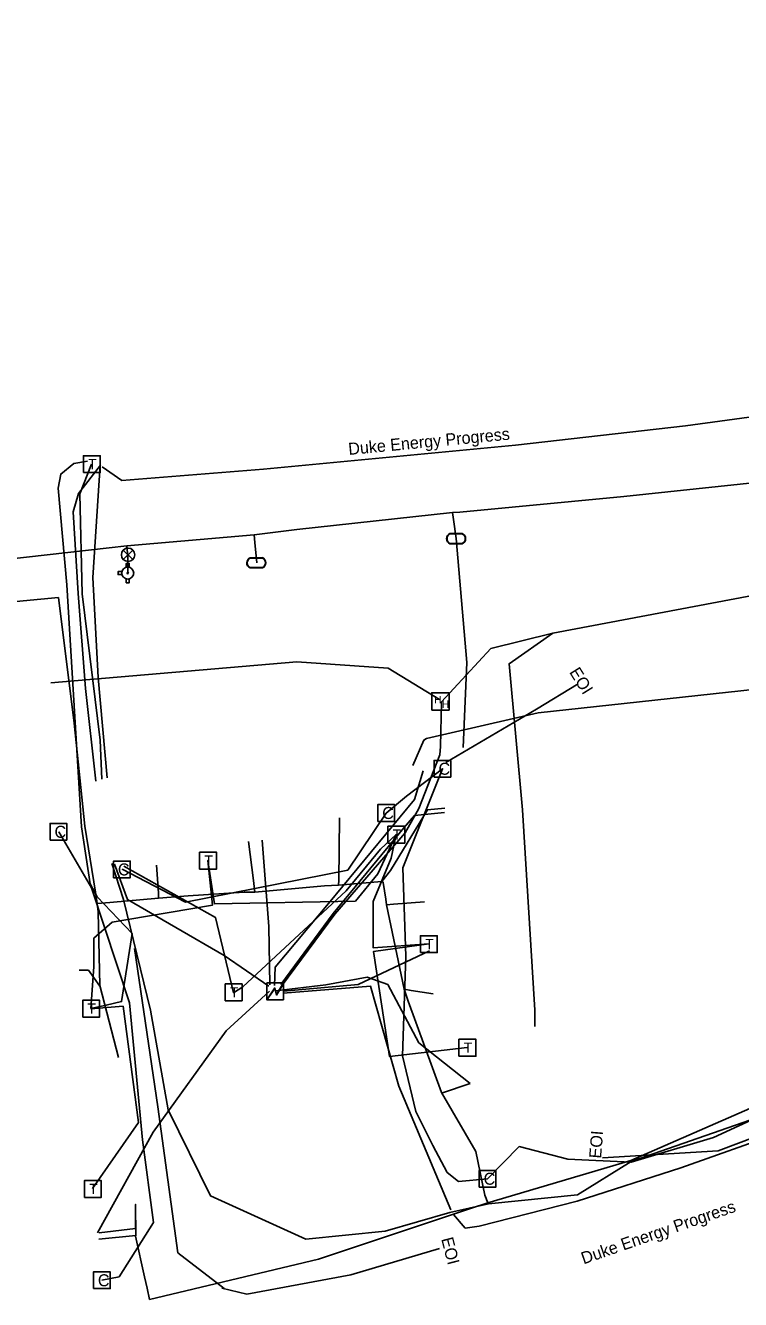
# Model space of a CAD drawing. Extents: x 2070721 to 2083340, y 729290 to 737883.
# Drawn here: x 2079795.9 to 2080033.2, y 734847.8 to 735270.6 of the extents above; entities that cross this region are included whole.
import ezdxf

# ---------------------------------------------------------------- set-up
doc = ezdxf.new("R2010")
doc.units = 0
for name, color, linetype in [('Exist Utilities Gas UG Line SUE LOS B', 7, 'Continuous'), ('Exist Utilities Other Pole Text', 7, 'Continuous'), ('Exist Utilities Other Unknown UG SUE LOS B', 7, 'Continuous'), ('Exist Utilities Power Hand Hole CELL', 7, 'Continuous'), ('Exist Utilities Power Transformer CELL', 7, 'Continuous'), ('Exist Utilities Power UG Cable SUE LOS B', 7, 'Continuous'), ('Exist Utilities Power UG Cable SUE LOS B Text', 7, 'Continuous'), ('Exist Utilities Telephone Pedestal CELL', 7, 'Continuous'), ('Exist Utilities Telephone UG Cable SUE LOS C', 7, 'Continuous'), ('Exist Utilities TV Pedestal CELL', 7, 'Continuous'), ('Exist Utilities TV Pedestal Text', 7, 'Continuous'), ('Exist Utilities TV UG Cable SUE LOS C', 7, 'Continuous'), ('Exist Utilities Water Fire Hydrant CELL', 7, 'Continuous'), ('Exist Utilities Water Meter CELL', 7, 'Continuous'), ('Exist Utilities Water UG Line SUE LOS B', 7, 'Continuous'), ('Exist Utilities Water Valve CELL', 7, 'Continuous')]:
    doc.layers.add(name, color=color, linetype=linetype)

msp = doc.modelspace()

# ---------------------------------------------------------------- linework, layer by layer
at = {"layer": 'Exist Utilities Gas UG Line SUE LOS B'}
for p, q in [((2079820.55, 734952.02), (2079826.75, 734928.16)), ((2079943.49, 734919.53), (2079934, 734916.34))]:
    msp.add_line(p, q, dxfattribs=at)
for points in [[(2079414.85, 735046.76), (2079454.13, 735049.75), (2079543.65, 735057.22), (2079599.14, 735062.31), (2079679.58, 735068.56), (2079761.05, 735076.49), (2079806.84, 735080.78), (2079812.03, 735039.09)], [(2079819.7, 734979.23), (2079819.1, 734983), (2079815.63, 735004.94), (2079812.03, 735039.09)], [(2079914.14, 734986.5), (2079917.04, 734990.19), (2079929.28, 735010.34), (2079935.11, 735010.83)], [(2079899.81, 734985.29), (2079899.84, 734986.97), (2079900.15, 735007.66)], [(2079871.98, 734983.03), (2079871.52, 734986.88), (2079869.95, 734999.87)], [(2079840.03, 734981.01), (2079840.09, 734982.77), (2079839.39, 734992.02)], [(2079899.81, 734985.29), (2079895.09, 734985.08), (2079871.98, 734983.03)], [(2079914.14, 734986.5), (2079899.81, 734985.29)], [(2079915.7, 734978.81), (2079915.49, 734980.72), (2079914.64, 734986.24), (2079914.14, 734986.5)], [(2079840.03, 734981.01), (2079823.9, 734979.6), (2079819.7, 734979.23)], [(2079871.98, 734983.03), (2079868.44, 734983.01), (2079849.88, 734981.79), (2079840.03, 734981.01)], [(2079819.7, 734979.23), (2079819.99, 734976.46), (2079820.55, 734952.02)], [(2079915.7, 734978.81), (2079918.01, 734979), (2079928.3, 734979.85)], [(2079921.53, 734950.78), (2079915.7, 734978.81)], [(2079820.54, 734951.86), (2079816.8, 734957.12), (2079813.68, 734957.12)], [(2079921.53, 734950.78), (2079923.85, 734950.38), (2079931.17, 734949.3)], [(2079949.32, 734879.97), (2079948.37, 734882.46), (2079945.4, 734896.93), (2079933.99, 734916.54), (2079922.96, 734946.84), (2079921.53, 734950.78)], [(2079949.32, 734879.97), (2079996.84, 734894.02), (2080044.13, 734914.6), (2080077.42, 734926.53), (2080123.41, 734941.95), (2080133.94, 734945)], [(2079820.34, 734869.93), (2079832.43, 734871.42), (2079832.43, 734879.38), (2079832.53, 734869.03), (2079820.22, 734867.89)], [(2079837.08, 734847.83), (2079893.1, 734861.27), (2079943.95, 734878.14), (2079949.32, 734879.97)], [(2079832.45, 734868.87), (2079835.42, 734855.37)], [(2079835.42, 734855.37), (2079836.25, 734851.6), (2079837.08, 734847.83)]]:
    msp.add_lwpolyline(points, dxfattribs=at)
at = {"layer": 'Exist Utilities Other Unknown UG SUE LOS B'}
for points in [[(2079964.93, 734938.4), (2079964.93, 734943.9), (2079960.87, 735010.33), (2079956.41, 735058.83), (2079970.93, 735068.94)], [(2079861.84, 734851.44), (2079846.5, 734863.35), (2079839.82, 734911.79), (2079832.04, 734964.37)], [(2079861.04, 734851.58), (2079869.33, 734849.63), (2079903.86, 734856.01), (2079933.32, 734864.79)]]:
    msp.add_lwpolyline(points, dxfattribs=at)
at = {"layer": 'Exist Utilities Power Hand Hole CELL'}
msp.add_line((2079933.68, 735046.14), (2079933.68, 735046.14), dxfattribs=at)
msp.add_lwpolyline([(2079930.73, 735043.41), (2079936.48, 735043.41), (2079936.48, 735049.16), (2079930.73, 735049.16), (2079930.73, 735043.41)], dxfattribs=at)
at = {"layer": 'Exist Utilities Power Transformer CELL'}
msp.add_line((2079878.82, 734950.25), (2079878.82, 734950.25), dxfattribs=at)
msp.add_lwpolyline([(2079875.97, 734952.87), (2079881.52, 734952.87), (2079881.52, 734947.31), (2079875.97, 734947.31)], close=True, dxfattribs=at)
for points in [[(2079875.97, 734947.31), (2079878.61, 734951.26), (2079879.24, 734949.05), (2079881.52, 734952.87)], [(2079876.04, 734947.31), (2079878.61, 734951.05), (2079879.2, 734948.87), (2079881.52, 734952.71)]]:
    msp.add_lwpolyline(points, dxfattribs=at)
at = {"layer": 'Exist Utilities Power UG Cable SUE LOS B'}
for points in [[(2079821.33, 735124.13), (2079827.86, 735119.63), (2079874.94, 735123.38), (2079958.5, 735131.34), (2080015, 735137.74), (2080088.94, 735147.78), (2080173.89, 735156.26), (2080200.11, 735169.56), (2080228.49, 735215.43), (2080246.93, 735270.61)], [(2079820.82, 735124.7), (2079813.52, 735115.34), (2079811.73, 735109.27), (2079813.4, 735082.17), (2079815.83, 735050.61), (2079819.25, 735019.8)], [(2079823, 735021), (2079819.99, 735054.23), (2079818.26, 735087.39), (2079820.67, 735124.76)], [(2079970.93, 735068.94), (2080060.68, 735085.85), (2080105.85, 735089.11), (2080166.83, 735095.38), (2080172.93, 735082.78)], [(2079933.65, 735031.31), (2079934.01, 735046.2), (2079950.34, 735063.83), (2079970.93, 735068.94)], [(2079929, 735034.01), (2079966.1, 735042.55), (2080052.65, 735051.87), (2080116.2, 735063.66), (2080127.54, 735054.13)], [(2079933.36, 735046.91), (2079916.26, 735057.31), (2079885.92, 735059.47), (2079804.25, 735052.53)], [(2079880.87, 734951.79), (2079898.59, 734975.74), (2079921.87, 735002.72), (2079926.41, 735010.81), (2079933.42, 735028.58), (2079933.65, 735031.31)], [(2079929, 735034.01), (2079928.11, 735033.48), (2079924.48, 735025.08)], [(2079927.87, 735023.3), (2079924.98, 735013.79), (2079896.42, 734979.23), (2079878.78, 734958.14), (2079878.49, 734952.06)], [(2079935.01, 735009.41), (2079924.98, 735008.45), (2079921.43, 735004.31), (2079897.96, 734975.94), (2079880.59, 734952.34)], [(2079877.01, 734952.22), (2079876.67, 734971.65), (2079874.43, 735000.27)], [(2079949.54, 734879.56), (2079936.72, 734876.68), (2079915.26, 734870.54), (2079888.89, 734867.91), (2079857.32, 734882.19), (2079843.23, 734910.76), (2079837.34, 734943.81), (2079828.44, 734980.63), (2079824.51, 734992.48)], [(2079825.39, 734992.25), (2079829.74, 734980.55), (2079861.87, 734961.95), (2079876.65, 734951.77)], [(2079881.57, 734950.14), (2079906.31, 734952.42), (2079930.02, 734963.54)], [(2079943.45, 734919.54), (2079926.4, 734933.05), (2079916.15, 734952.37), (2079909.35, 734954.83), (2079895.57, 734952.25), (2079878.82, 734950.25)], [(2079881.41, 734949.51), (2079910.44, 734951.78), (2079919.8, 734918.62), (2079937.05, 734877.55)], [(2079876.86, 734950.12), (2079862.49, 734936.96), (2079838.26, 734903.35), (2079819.82, 734869.91)], [(2079949.54, 734879.56), (2079979.11, 734882.53), (2079996.9, 734893.62), (2080046.16, 734910.81), (2080070.87, 734920.4), (2080091.91, 734922.1), (2080094.14, 734922.76), (2080121.97, 734932.67), (2080134.03, 734940.16), (2080135.53, 734941.3), (2080137.12, 734943.43), (2080137.09, 734946.33)], [(2079987.46, 734894.8), (2080025.82, 734897.12), (2080069.48, 734913.65), (2080069.5, 734913.41), (2080092.72, 734923.35), (2080113.03, 734931.23), (2080133.81, 734940.47), (2080134.5, 734941.28), (2080135.67, 734943.18), (2080136.32, 734946.38)], [(2080070.67, 734913.66), (2080046.49, 734903.28), (2080013.44, 734891.52), (2079979.04, 734880.46), (2079946.47, 734872.13), (2079941.84, 734871.56), (2079937.96, 734876.06)]]:
    msp.add_lwpolyline(points, dxfattribs=at)
at = {"layer": 'Exist Utilities Telephone Pedestal CELL'}
for p, q in [((2079817.84, 735125.07), (2079817.84, 735125.07)), ((2079918.9, 735002.11), (2079918.9, 735002.11)), ((2079856.43, 734993.49), (2079856.43, 734993.49)), ((2079929.7, 734965.76), (2079929.7, 734965.76)), ((2079864.91, 734949.77), (2079864.91, 734949.77)), ((2079817.61, 734944.38), (2079817.61, 734944.38)), ((2079942.5, 734931.41), (2079942.5, 734931.41)), ((2079818.16, 734884.53), (2079818.16, 734884.53))]:
    msp.add_line(p, q, dxfattribs=at)
for points in [[(2079815.11, 735122.24), (2079820.71, 735122.24), (2079820.71, 735127.84), (2079815.11, 735127.84), (2079815.11, 735122.24)], [(2079916.18, 734999.28), (2079921.77, 734999.28), (2079921.77, 735004.88), (2079916.18, 735004.88), (2079916.18, 734999.28)], [(2079853.7, 734990.67), (2079859.3, 734990.67), (2079859.3, 734996.26), (2079853.7, 734996.26), (2079853.7, 734990.67)], [(2079926.98, 734962.94), (2079932.57, 734962.94), (2079932.57, 734968.53), (2079926.98, 734968.53), (2079926.98, 734962.94)], [(2079862.18, 734946.95), (2079867.78, 734946.95), (2079867.78, 734952.54), (2079862.18, 734952.54), (2079862.18, 734946.95)], [(2079814.88, 734941.56), (2079820.48, 734941.56), (2079820.48, 734947.15), (2079814.88, 734947.15), (2079814.88, 734941.56)], [(2079939.78, 734928.58), (2079945.37, 734928.58), (2079945.37, 734934.18), (2079939.78, 734934.18), (2079939.78, 734928.58)], [(2079815.44, 734881.71), (2079821.03, 734881.71), (2079821.03, 734887.3), (2079815.44, 734887.3), (2079815.44, 734881.71)]]:
    msp.add_lwpolyline(points, dxfattribs=at)
at = {"layer": 'Exist Utilities Telephone UG Cable SUE LOS C'}
msp.add_line((2079816.51, 735126), (2079811.96, 735125.25), dxfattribs=at)
for points in [[(2079817.61, 734944.38), (2079822.67, 734945.46), (2079827.77, 734946.69), (2079831.29, 734969.34), (2079819.71, 734981.48), (2079817.33, 734985.82), (2079814.49, 735004.64), (2079809.64, 735084.95), (2079806.69, 735117.1), (2079807.59, 735121.72), (2079811.96, 735125.25)], [(2079821.27, 735020.53), (2079820.66, 735033.5), (2079814.75, 735081.99), (2079813.89, 735115.23), (2079817.83, 735125.07)], [(2079918.9, 735002.11), (2079912.79, 734989.12), (2079905.4, 734980.06), (2079858.58, 734979.14), (2079856.42, 734993.56), (2079857.94, 734978.69), (2079836.42, 734975.05), (2079824.67, 734973.1), (2079818.6, 734967.8), (2079818.6, 734958.21), (2079817.61, 734944.38)], [(2079828.5, 734991.62), (2079858.93, 734974.65), (2079864.89, 734949.65), (2079868.05, 734951.56), (2079902.35, 734983.45), (2079913.68, 734997.32), (2079918.9, 735002.14), (2079917.23, 734994.34), (2079911.29, 734979.95), (2079911.33, 734964.51), (2079929.81, 734965.81), (2079911.43, 734963.36), (2079916.73, 734928.46), (2079942.45, 734931.48)], [(2079818.15, 734884.62), (2079833.35, 734906.59), (2079828.26, 734945.18), (2079817.57, 734944.24)]]:
    msp.add_lwpolyline(points, dxfattribs=at)
at = {"layer": 'Exist Utilities TV Pedestal CELL'}
for p, q in [((2079934.29, 735023.96), (2079934.29, 735023.96)), ((2079915.6, 735009.28), (2079915.6, 735009.28)), ((2079806.81, 735003.04), (2079806.81, 735003.04)), ((2079827.88, 734990.55), (2079827.88, 734990.55)), ((2079949.27, 734887.92), (2079949.27, 734887.92)), ((2079821.23, 734854.21), (2079821.23, 734854.21))]:
    msp.add_line(p, q, dxfattribs=at)
for points in [[(2079931.51, 735021.19), (2079937.06, 735021.19), (2079937.06, 735026.74), (2079931.51, 735026.74), (2079931.51, 735021.19)], [(2079912.83, 735006.51), (2079918.38, 735006.51), (2079918.38, 735012.06), (2079912.83, 735012.06), (2079912.83, 735006.51)], [(2079804.04, 735000.27), (2079809.59, 735000.27), (2079809.59, 735005.82), (2079804.04, 735005.82), (2079804.04, 735000.27)], [(2079825.1, 734987.78), (2079830.65, 734987.78), (2079830.65, 734993.33), (2079825.1, 734993.33), (2079825.1, 734987.78)], [(2079946.5, 734885.15), (2079952.05, 734885.15), (2079952.05, 734890.7), (2079946.5, 734890.7), (2079946.5, 734885.15)], [(2079818.46, 734851.44), (2079824.01, 734851.44), (2079824.01, 734856.99), (2079818.46, 734856.99), (2079818.46, 734851.44)]]:
    msp.add_lwpolyline(points, dxfattribs=at)
at = {"layer": 'Exist Utilities TV UG Cable SUE LOS C'}
for points in [[(2079935.37, 735026.02), (2079965.55, 735043.69), (2079979.35, 735052.1)], [(2079827.95, 734990.62), (2079849.02, 734979.74), (2079902.83, 734990.26), (2079915.57, 735009.2), (2079922.31, 735014.82), (2079934.31, 735023.97), (2079921.14, 734991.04), (2079922.13, 734961.81), (2079921.05, 734928.69), (2079925.47, 734910.25), (2079931.06, 734898.98), (2079935.82, 734890.03), (2079939.57, 734887), (2079949.27, 734887.92)], [(2079806.9, 735003.08), (2079817.75, 734984.43), (2079830.39, 734946.28), (2079834.72, 734900.79), (2079838.43, 734873.38), (2079826.93, 734855.34), (2079821.22, 734854.31)], [(2079949.24, 734887.87), (2079959.74, 734898.59), (2079975.94, 734894.45), (2079996.9, 734893.38), (2080024.24, 734901.56), (2080063.46, 734919.58), (2080075.63, 734929.35), (2080104.34, 734945.04), (2080121.88, 734961.24)]]:
    msp.add_lwpolyline(points, dxfattribs=at)
at = {"layer": 'Exist Utilities Water Fire Hydrant CELL'}
msp.add_line((2079829.83, 735088.89), (2079829.83, 735088.89), dxfattribs=at)
for points in [[(2079829.32, 735090.81), (2079829.32, 735092.09), (2079830.34, 735092.09), (2079830.34, 735090.78)], [(2079827.92, 735089.41), (2079826.63, 735089.41), (2079826.63, 735088.38), (2079827.92, 735088.38)], [(2079829.32, 735086.98), (2079829.32, 735085.69), (2079830.34, 735085.69), (2079830.34, 735087.01)]]:
    msp.add_lwpolyline(points, dxfattribs=at)
for radius in [1.98, 0.243]:
    msp.add_circle((2079829.83, 735088.89), radius, dxfattribs=at)
at = {"layer": 'Exist Utilities Water Meter CELL'}
for p, q in [((2079938.82, 735100.31), (2079938.82, 735100.31)), ((2079872.5, 735092.31), (2079872.5, 735092.31))]:
    msp.add_line(p, q, dxfattribs=at)
for points in [[(2079940.86, 735098.75), (2079936.76, 735098.75)], [(2079940.86, 735098.61), (2079936.76, 735098.61)], [(2079936.78, 735102.01), (2079940.86, 735102.01)], [(2079936.78, 735101.88), (2079940.86, 735101.88)], [(2079874.54, 735090.75), (2079870.44, 735090.75)], [(2079874.54, 735090.61), (2079870.44, 735090.61)], [(2079870.46, 735094.01), (2079874.54, 735094.01)], [(2079870.46, 735093.87), (2079874.54, 735093.87)]]:
    msp.add_lwpolyline(points, dxfattribs=at)
for centre, radius, start, end in [((2079937.51, 735100.31), 1.86, 113.178, 245.9794), ((2079937.53, 735100.31), 1.73, 115.3009, 243.7824), ((2079940.11, 735100.31), 1.86, 293.6483, 66.3084), ((2079940.13, 735100.31), 1.73, 295.1272, 64.8728), ((2079871.19, 735092.3), 1.86, 113.178, 245.9794), ((2079871.21, 735092.3), 1.73, 115.3009, 243.7824), ((2079873.79, 735092.31), 1.86, 293.6483, 66.3084), ((2079873.81, 735092.31), 1.73, 295.1272, 64.8728)]:
    msp.add_arc(centre, radius, start, end, dxfattribs=at)
at = {"layer": 'Exist Utilities Water UG Line SUE LOS B'}
for points in [[(2079937.59, 735108.95), (2079940.07, 735109.15), (2079994.44, 735114.29), (2080071.74, 735122.47)], [(2079871.83, 735101.56), (2079886, 735103.41), (2079937.59, 735108.95)], [(2079937.59, 735108.95), (2079937.93, 735106.67), (2079938.88, 735100.36)], [(2079829.56, 735097.92), (2079871.83, 735101.56)], [(2079871.83, 735101.56), (2079872.06, 735099.08), (2079872.67, 735092.35)], [(2079941.2, 735030.98), (2079942.38, 735059.26), (2079938.88, 735100.36)], [(2079782.41, 735092.68), (2079823.71, 735097.22), (2079829.56, 735097.92)], [(2079829.56, 735097.92), (2079829.76, 735095.55), (2079829.87, 735094.94), (2079829.86, 735088.82)]]:
    msp.add_lwpolyline(points, dxfattribs=at)
at = {"layer": 'Exist Utilities Water Valve CELL'}
msp.add_lwpolyline([(2079831.51, 735096.55), (2079828.36, 735093.4), (2079829.93, 735094.97), (2079831.51, 735093.4), (2079828.36, 735096.55)], dxfattribs=at)
msp.add_circle((2079829.93, 735094.97), 2.23, dxfattribs=at)

# ---------------------------------------------------------------- texts
at = {"layer": 'Exist Utilities Other Pole Text'}
for rotation, p in [(85.478, (2079986.93, 734894.53)), (284.6363, (2079933.84, 734867.94))]:
    msp.add_text('EOI', height=4, rotation=rotation, dxfattribs=at).set_placement(p)
at = {"layer": 'Exist Utilities Power Hand Hole CELL'}
for p in [(2079931.52, 735045.66), (2079934.09, 735044.14)]:
    msp.add_text('H', height=2.5, dxfattribs=at).set_placement(p)
at = {"layer": 'Exist Utilities Power UG Cable SUE LOS B Text'}
for rotation, p in [(5.4439, (2079903.22, 735128.08)), (19.0961, (2079981.14, 734859.48))]:
    msp.add_text('Duke Energy Progress', height=4, rotation=rotation, dxfattribs=at).set_placement(p)
at = {"layer": 'Exist Utilities Telephone Pedestal CELL'}
for p in [(2079816.71, 735123.36), (2079917.77, 735000.4), (2079855.3, 734991.78), (2079928.57, 734964.05), (2079863.78, 734948.06), (2079816.47, 734942.67), (2079941.37, 734929.7), (2079817.03, 734882.82)]:
    msp.add_text('T', height=3.42, dxfattribs=at).set_placement(p)
at = {"layer": 'Exist Utilities TV Pedestal CELL'}
for p in [(2079932.98, 735021.96), (2079914.3, 735007.28), (2079805.51, 735001.04), (2079826.57, 734988.55), (2079947.96, 734885.92), (2079819.92, 734852.21)]:
    msp.add_text('C', height=4, dxfattribs=at).set_placement(p)
at = {"layer": 'Exist Utilities TV Pedestal Text'}
msp.add_text('EOI', height=4, rotation=301.8516, dxfattribs=at).set_placement((2079976.26, 735056.04))

doc.saveas('drawing.dxf')
